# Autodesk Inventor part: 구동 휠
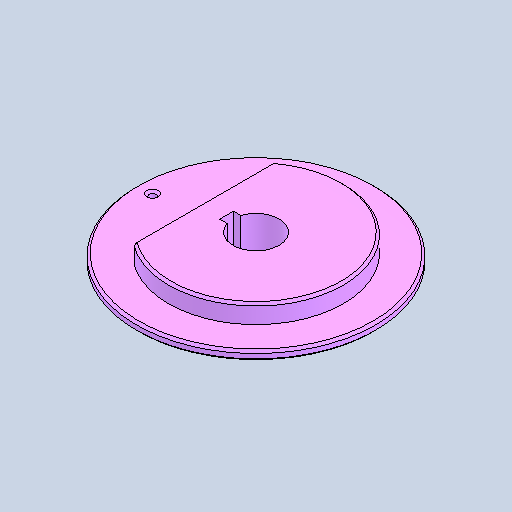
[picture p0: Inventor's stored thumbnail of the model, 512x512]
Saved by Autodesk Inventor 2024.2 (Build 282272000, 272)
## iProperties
Created: 2025-09
Part Number: 구동 휠
Material: 강철, 연강
Document SubType Name: Modeling
Designer: home
Density: 7.85 g/cm^3
Appearance: 기본값
Author: jhkim
Sending System: Autodesk Inventor 2026
Preprocessor: ST-DEVELOPER v20.1
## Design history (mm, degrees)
feature "솔리드1"
node "솔리드2"
